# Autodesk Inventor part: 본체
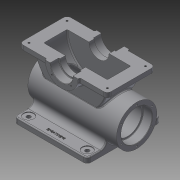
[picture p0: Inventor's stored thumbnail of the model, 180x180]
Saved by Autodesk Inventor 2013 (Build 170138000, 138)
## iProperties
Created: 2023-06
Part Number: 본체
Material: 일반
Document SubType Name: Modeling
Designer: mdu-01
Mass: 5644.39 g
Surface Area: 2847.06 cm^2
Volume: 2082.8 cm^3
Density: 2.71 g/cm^3
Author: mdu-01
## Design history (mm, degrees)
sketch "스케치1"
  geometry: L1 (0, 70)-(0, -70); L2 (0, 0)-(-100, 0); L3 (0, 70)-(-45, 70); L4 (-45, 70)-(-45, 45); L5 (-45, 45)-(-100, 45); L6 (0, -70)-(-45, -70); L7 (-45, -70)-(-45, -45); L8 (-45, -45)-(-100, -45); L9 (-100, 45)-(-100, -45); 1 further point
  constraints: 18 end point, 3 perpendicular, 3 symmetric about line, 2 midpoint, 2 parallel, 1 coincident, 1 vertical
  dimensions: "d0" = 140 distance of L1.start L1.end; "d1" = 100 distance of L2.start L2.end; "d3" = 90 diameter of L4 L1; "d4" = 90 distance between parallel lines of L8 L5
revolve "회전1" sketch "스케치1" stored, may be unused: angle "d5" = 180 deg
sketch "스케치2"
  geometry: L1 (-155, -20)-(65, -20); L2 (75, -10)-(75, 100); L3 (65, 110)-(-155, 110); L4 (-165, 100)-(-165, -10); L5 (-165, -20)-(75, 110); L6 (75, -20)-(-165, 110); A1 r 10 centre (-155, 100) between (-155, 110) and (-165, 100); A2 r 10 centre (65, 100) between (75, 100) and (65, 110); A3 r 10 centre (65, -10) between (65, -20) and (75, -10); A4 r 10 centre (-155, -10) between (-165, -10) and (-155, -20); 1 further point
  constraints: 12 end point, 8 point on circle, 8 point on line, 8 tangent, 4 centre point, 3 equal radius, 2 midpoint, 2 parallel, 1 horizontal, 1 perpendicular
  dimensions: "d6" = 240 distance of L6.end L5.end; "d7" = 130 distance of L5.end L6.start; "d8" = 10 radius of A1
extrude "돌출1" join sketch "스케치2" distance "d9" = 15; taper "d10" = 0 deg
sketch "스케치3"
  geometry: C1 r 55 at (-100, 0); 1 further point
  constraints: 1 centre point
  dimensions: "d11" = 110 diameter of C1; "d12" = 100 distance of C1.centre point (0, 0)
extrude "돌출2" join sketch "스케치3" distance "d13" = 135; taper "d15" = 0 deg; dims "d14" = 107, "d16" = 0
sketch "스케치4"
  geometry: L1 (-100, -160)-(100, -160); L2 (100, -160)-(100, -145); L3 (100, -145)-(-100, -145); L4 (-100, -145)-(-100, -160); 1 further point
  constraints: 8 end point, 2 parallel, 1 horizontal, 1 perpendicular
  dimensions: "d17" = 200 distance of L3.end L2.end; "d18" = 15 distance of L2.end L1.end; "d19" = 100 distance from line of L4 point (0, 0); "d20" = 160 distance from line of L1 point (0, 0)
extrude "돌출3" join sketch "스케치4" stored distance "d21" = 200; taper "d22" = 0 deg
fillet "모깎기1" dims "d23" = 15
fillet "모깎기2" dims "d24" = 10
sketch "스케치5"
  geometry: L1 (0, 70)-(0, -70); L2 (-45, 70)-(0, 70) reference; L3 (-45, -70)-(0, -70) reference; L4 (-31, 70)-(-31, 48); L5 (-30, 47)-(-27.5, 47); L6 (-27.5, 47)-(-27.5, 32); L7 (-27.5, 32)-(-87, 32); L8 (0, 0)-(-91.923, 0); L9 (-31, -70)-(-31, -48); L10 (-30, -47)-(-27.5, -47); L11 (-27.5, -47)-(-27.5, -32); L12 (-27.5, -32)-(-87, -32); L13 (-87, 32)-(-87, -32); L14 (-31, 70)-(0, 70); L15 (-31, -70)-(0, -70); A1 r 1 centre (-30, 48) between (-31, 48) and (-30, 47); A2 r 1 centre (-30, -48) between (-30, -47) and (-31, -48)
  constraints: 26 end point, 7 symmetric about line, 4 parallel, 4 point on circle, 3 perpendicular, 2 centre point, 2 tangent, 1 collinear, 1 point on line, 1 vertical, 1 other
  dimensions: "d25" = 1 radius of A1; "d26" = 62 diameter of L4 L1; "d27" = 23 distance between parallel lines of L2 L5; "d28" = 64 distance between parallel lines of L12 L7; "d29" = 55 diameter of L6 L1; "d30" = 87 distance between parallel lines of L13 L1
revolve "회전2" sketch "스케치5" stored, may be unused: angle "d31" = 180 deg
sketch "스케치6"
  geometry: L1 (-107, -45)-(-107, -155) reference; L2 (135, -155)-(135, -45) reference; L3 (-107, -100)-(135, -100); L4 (-107, -142.5)-(-83.1, -142.5); L5 (-82, -141.4)-(-82, -138.5); L6 (-82, -138.5)-(110, -138.5); L7 (110, -138.5)-(110, -141.4); L8 (111.1, -142.5)-(135, -142.5); A1 r 1.1 centre (-83.1, -141.4) between (-83.1, -142.5) and (-82, -141.4); A2 r 1.1 centre (111.1, -141.4) between (110, -141.4) and (111.1, -142.5); 1 further point
  constraints: 12 end point, 4 point on circle, 4 tangent, 3 parallel, 2 centre point, 2 collinear, 2 midpoint, 2 perpendicular, 2 point on line, 1 equal radius
  dimensions: "d32" = 1.1 radius of A1; "d33" = 25 distance between parallel lines of L5 L1; "d34" = 77 diameter of L6 L3; "d35" = 85 diameter of L4 L3
revolve "회전3" sketch "스케치6" stored, may be unused: angle "d36" = 180 deg
fillet "모깎기3" dims "d37" = 3
fillet "모깎기4" dims "d38" = 3
sketch "스케치7"
  geometry: L1 (17, -16.754)-(177, -16.754); L2 (177, -16.754)-(177, 143.246); L3 (177, 143.246)-(17, 143.246); L4 (17, 143.246)-(17, -16.754); L5 (17, -16.754)-(177, 143.246); L6 (177, -16.754)-(17, 143.246); 1 further point
  constraints: 12 end point, 2 midpoint, 2 parallel, 1 horizontal, 1 perpendicular
  dimensions: "d39" = 160 distance of L3.end L2.end; "d40" = 160 distance of L2.end L1.end
hole "구멍1" sketch "스케치7" at (17, -16.754), (177, -16.754), (177, 143.246), (17, 143.246) diameter "d41" = 11; stored, may be unused: countersink angle "d45" = 90 deg, drill point angle "d47" = 118 deg; dims "d42" = 6, "d43" = 28, "d44" = 2, "d46" = 8
sketch "스케치8"
  geometry: L1 (-227, 3)-(-13, 3); L2 (-13, 3)-(-13, 107); L3 (-13, 107)-(-227, 107); L4 (-227, 107)-(-227, 3); L5 (-227, 3)-(-13, 107); L6 (-13, 3)-(-227, 107); 1 further point
  constraints: 12 end point, 2 midpoint, 2 parallel, 1 horizontal, 1 perpendicular
  dimensions: "d48" = 214 distance of L3.end L2.end; "d49" = 104 distance of L2.end L1.end
hole "구멍2" sketch "스케치8" at (-227, 3), (-13, 3), (-13, 107), (-227, 107) diameter "d50" = 4.917; stored, may be unused: countersink angle "d54" = 90 deg, drill point angle "d56" = 118 deg; dims "d51" = 15, "d52" = 4, "d53" = 7.5, "d55" = 15
sketch "스케치9"
  geometry: A1 r 37 centre (0, 0) between (-26.163, -26.163) and (26.163, -26.163); 1 further point
  constraints: 2 point on circle, 1 centre point, 1 coincident, 1 horizontal alignment
  dimensions: "d57" = 37 radius of A1; "d58" = 90 deg dimension on A1.centre A1.end A1.start
hole "구멍3" sketch "스케치9" at (-26.163, -26.163), (26.163, -26.163) diameter "d60" = 4.134; stored, may be unused: countersink angle "d64" = 90 deg, drill point angle "d66" = 118 deg; dims "d61" = 10, "d62" = 4, "d63" = 7.5, "d65" = 12
sketch "스케치10" dims "d68" = 97
  geometry: C1 r 38.5 at (0, 0) reference; 3 further points
  constraints: 2 vertical alignment, 1 coincident, 2 other
hole "구멍4" sketch "스케치10" at (0, 48.5) diameter "d70" = 4.134; stored, may be unused: countersink angle "d74" = 90 deg, drill point angle "d76" = 118 deg; dims "d71" = 10, "d72" = 4, "d73" = 7.5, "d75" = 12
node "작업 평면1"
sketch "스케치11"
  geometry: L1 (7, -36.754)-(187, -36.754) reference; 2 further points
  constraints: 1 vertical alignment, 1 other
  dimensions: "d80" = 15 distance from line of point (97, -21.754) L1
feature "엠보싱1" sketch "스케치11" dims "d0" = 140, "d1" = 100, "d3" = 90, "d4" = 90, "d6" = 240, "d7" = 130, "d8" = 10, "d81" = 0.5, "d82" = 0
chamfer "모따기1" distance "d83" = 1; stored, may be unused: second distance "d84" = 2, angle "d85" = 45 deg
node "솔리드1"
mirror "대칭1"
pattern_circular "원형 패턴1" dims angle "d78" = 360 deg
mirror "대칭2"
